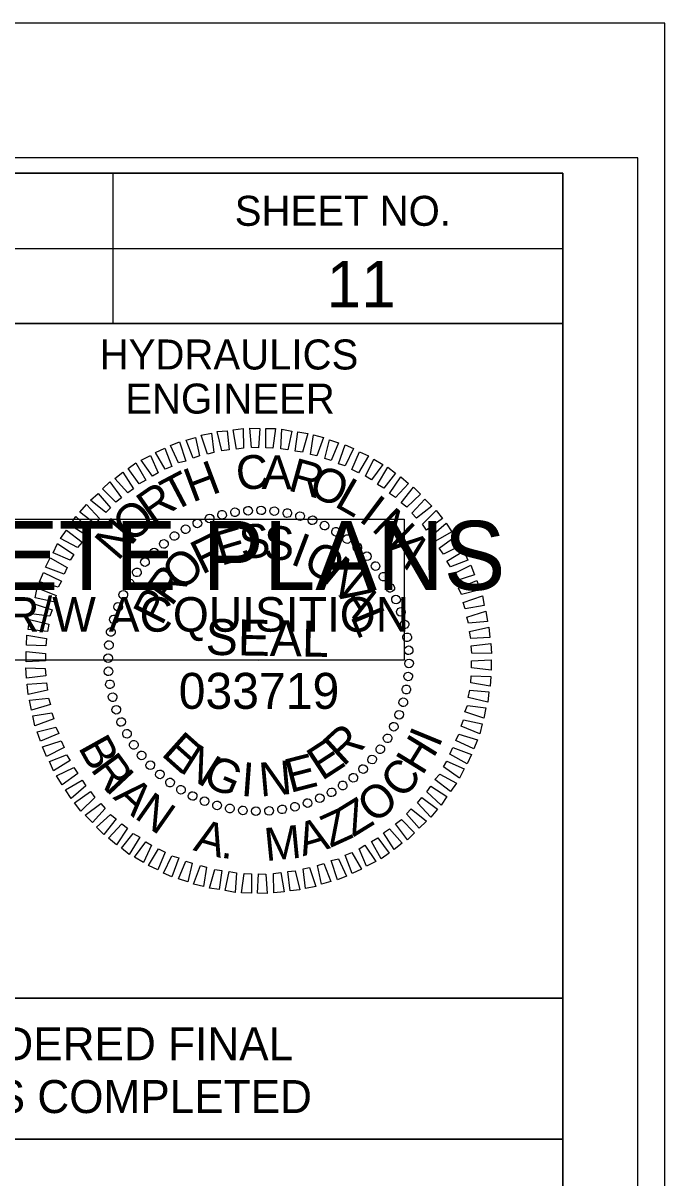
# Model space of a CAD drawing. Extents: x 1779926 to 1781610, y 620464 to 621564.
# Drawn here: x 1781503 to 1781610, y 621371.7 to 621564.2 of the extents above; entities that cross this region are included whole.
import ezdxf

# ---------------------------------------------------------------- set-up
doc = ezdxf.new("R2010")
doc.units = 0
for name, color, linetype in [('Old_Level_58', 7, 'Continuous'), ('Sheet Cutting Line CELL', 7, 'Continuous'), ('Sheet Data Field CELL', 7, 'Continuous'), ('Sheet Plot Border Inside CELL', 7, 'Continuous'), ('Sheet Plot Border Outside CELL', 7, 'Continuous'), ('Sheet Professional Seal CELL', 7, 'Continuous'), ('Sheet Profile CELL', 7, 'Continuous'), ('Sheet Profile Grid Major CELL', 7, 'Continuous'), ('Sheet Profile Grid Minor CELL', 7, 'Continuous'), ('Sheet Sticker Exception Certification CELL', 7, 'Continuous'), ('Sheet Sticker Incomplete CELL', 7, 'Continuous')]:
    doc.layers.add(name, color=color, linetype=linetype)

msp = doc.modelspace()

# ---------------------------------------------------------------- linework, layer by layer
at = {"layer": 'Old_Level_58'}
msp.add_lwpolyline([(1781392.96, 621378.13), (1781592.95, 621378.13), (1781592.95, 621314.19), (1781392.96, 621314.19)], close=True, dxfattribs=at)
at = {"layer": 'Sheet Cutting Line CELL'}
msp.add_line((1781609.96, 621564.19), (1779925.96, 621564.19), dxfattribs=at)
at = {"layer": 'Sheet Plot Border Inside CELL'}
msp.add_lwpolyline([(1779938.96, 620486.64), (1781605.46, 620486.64), (1781605.46, 621541.74), (1779938.96, 621541.74)], close=True, dxfattribs=at)
at = {"layer": 'Sheet Plot Border Outside CELL'}
msp.add_lwpolyline([(1779925.96, 620464.19), (1781609.96, 620464.19), (1781609.96, 621564.19), (1779925.96, 621564.19)], close=True, dxfattribs=at)
at = {"layer": 'Sheet Professional Seal CELL'}
for p, q in [((1781538.34, 621482.64), (1781538.34, 621482.64)), ((1781540.49, 621482.94), (1781540.49, 621482.94)), ((1781542.69, 621482.99), (1781542.69, 621482.99)), ((1781544.89, 621482.84), (1781544.89, 621482.84)), ((1781547.04, 621482.49), (1781547.04, 621482.49)), ((1781532.04, 621480.84), (1781532.04, 621480.84)), ((1781534.04, 621481.64), (1781534.04, 621481.64)), ((1781536.14, 621482.24), (1781536.14, 621482.24)), ((1781549.14, 621482.04), (1781549.14, 621482.04)), ((1781551.24, 621481.34), (1781551.24, 621481.34)), ((1781528.19, 621478.69), (1781528.19, 621478.69)), ((1781530.09, 621479.84), (1781530.09, 621479.84)), ((1781553.24, 621480.44), (1781553.24, 621480.44)), ((1781555.19, 621479.44), (1781555.19, 621479.44)), ((1781526.44, 621477.44), (1781526.44, 621477.44)), ((1781556.99, 621478.19), (1781556.99, 621478.19)), ((1781558.74, 621476.84), (1781558.74, 621476.84)), ((1781524.79, 621475.94), (1781524.79, 621475.94)), ((1781560.29, 621475.34), (1781560.29, 621475.34)), ((1781523.29, 621474.39), (1781523.29, 621474.39)), ((1781561.79, 621473.69), (1781561.79, 621473.69)), ((1781521.94, 621472.64), (1781521.94, 621472.64)), ((1781563.04, 621471.94), (1781563.04, 621471.94)), ((1781520.69, 621470.84), (1781520.69, 621470.84)), ((1781564.19, 621470.04), (1781564.19, 621470.04)), ((1781519.69, 621468.89), (1781519.69, 621468.89)), ((1781565.19, 621468.09), (1781565.19, 621468.09)), ((1781518.79, 621466.89), (1781518.79, 621466.89)), ((1781565.99, 621466.09), (1781565.99, 621466.09)), ((1781518.09, 621464.79), (1781518.09, 621464.79)), ((1781566.59, 621463.99), (1781566.59, 621463.99)), ((1781517.64, 621462.69), (1781517.64, 621462.69)), ((1781566.99, 621461.79), (1781566.99, 621461.79)), ((1781517.29, 621460.54), (1781517.29, 621460.54)), ((1781567.29, 621459.64), (1781567.29, 621459.64)), ((1781517.14, 621458.34), (1781517.14, 621458.34)), ((1781542.24, 621457.89), (1781542.24, 621457.89)), ((1781567.34, 621457.44), (1781567.34, 621457.44)), ((1781517.19, 621456.14), (1781517.19, 621456.14)), ((1781517.49, 621453.99), (1781517.49, 621453.99)), ((1781567.19, 621455.24), (1781567.19, 621455.24)), ((1781517.89, 621451.79), (1781517.89, 621451.79)), ((1781566.84, 621453.09), (1781566.84, 621453.09)), ((1781518.49, 621449.69), (1781518.49, 621449.69)), ((1781566.39, 621450.99), (1781566.39, 621450.99)), ((1781565.69, 621448.89), (1781565.69, 621448.89)), ((1781519.29, 621447.69), (1781519.29, 621447.69)), ((1781564.79, 621446.89), (1781564.79, 621446.89)), ((1781520.29, 621445.74), (1781520.29, 621445.74)), ((1781563.79, 621444.94), (1781563.79, 621444.94)), ((1781521.44, 621443.84), (1781521.44, 621443.84)), ((1781522.69, 621442.09), (1781522.69, 621442.09)), ((1781562.54, 621443.14), (1781562.54, 621443.14)), ((1781524.19, 621440.44), (1781524.19, 621440.44)), ((1781561.19, 621441.39), (1781561.19, 621441.39)), ((1781525.74, 621438.94), (1781525.74, 621438.94)), ((1781558.04, 621438.34), (1781558.04, 621438.34)), ((1781559.69, 621439.84), (1781559.69, 621439.84)), ((1781527.49, 621437.59), (1781527.49, 621437.59)), ((1781529.29, 621436.34), (1781529.29, 621436.34)), ((1781556.29, 621437.09), (1781556.29, 621437.09)), ((1781531.24, 621435.34), (1781531.24, 621435.34)), ((1781533.24, 621434.44), (1781533.24, 621434.44)), ((1781552.44, 621434.94), (1781552.44, 621434.94)), ((1781554.39, 621435.94), (1781554.39, 621435.94)), ((1781535.34, 621433.74), (1781535.34, 621433.74)), ((1781537.44, 621433.29), (1781537.44, 621433.29)), ((1781539.59, 621432.94), (1781539.59, 621432.94)), ((1781541.79, 621432.79), (1781541.79, 621432.79)), ((1781543.99, 621432.84), (1781543.99, 621432.84)), ((1781546.14, 621433.14), (1781546.14, 621433.14)), ((1781548.34, 621433.54), (1781548.34, 621433.54)), ((1781550.44, 621434.14), (1781550.44, 621434.14))]:
    msp.add_line(p, q, dxfattribs=at)
for points in [[(1781536.14, 621492.89), (1781535.34, 621496.09), (1781536.99, 621496.24), (1781537.34, 621493.04)], [(1781538.54, 621493.19), (1781537.99, 621496.39), (1781539.69, 621496.59), (1781539.74, 621493.34)], [(1781541.04, 621493.44), (1781540.79, 621496.69), (1781542.44, 621496.64), (1781542.24, 621493.39)], [(1781543.44, 621493.39), (1781543.44, 621496.64), (1781545.09, 621496.59), (1781544.64, 621493.34)], [(1781545.94, 621493.24), (1781546.14, 621496.49), (1781547.79, 621496.19), (1781547.14, 621493.04)], [(1781548.34, 621492.84), (1781548.79, 621496.04), (1781550.44, 621495.79), (1781549.54, 621492.69)], [(1781528.89, 621490.89), (1781527.59, 621493.79), (1781529.09, 621494.39), (1781530.14, 621491.19)], [(1781531.34, 621491.69), (1781530.19, 621494.69), (1781531.74, 621495.14), (1781532.39, 621492.04)], [(1781533.74, 621492.34), (1781532.69, 621495.49), (1781534.39, 621495.84), (1781534.79, 621492.59)], [(1781550.89, 621492.29), (1781551.39, 621495.54), (1781553.09, 621495.14), (1781551.94, 621492.04)], [(1781553.29, 621491.64), (1781554.04, 621494.74), (1781555.59, 621494.24), (1781554.34, 621491.29)], [(1781524.54, 621488.64), (1781522.69, 621491.34), (1781524.24, 621492.14), (1781525.49, 621489.24)], [(1781526.69, 621489.84), (1781525.09, 621492.64), (1781526.64, 621493.34), (1781527.79, 621490.29)], [(1781555.54, 621490.74), (1781556.69, 621493.89), (1781558.09, 621493.29), (1781556.69, 621490.39)], [(1781557.79, 621489.79), (1781559.04, 621492.74), (1781560.59, 621492.04), (1781558.89, 621489.24)], [(1781522.34, 621487.39), (1781520.49, 621489.94), (1781521.79, 621490.89), (1781523.44, 621487.99)], [(1781560.09, 621488.64), (1781561.44, 621491.49), (1781562.94, 621490.64), (1781561.04, 621488.04)], [(1781562.04, 621487.29), (1781563.79, 621490.19), (1781565.09, 621489.14), (1781563.14, 621486.69)], [(1781520.44, 621485.89), (1781518.29, 621488.29), (1781519.64, 621489.34), (1781521.39, 621486.54)], [(1781564.09, 621485.79), (1781565.94, 621488.54), (1781567.24, 621487.44), (1781565.04, 621485.09)], [(1781518.44, 621484.34), (1781516.24, 621486.54), (1781517.44, 621487.74), (1781519.39, 621485.04)], [(1781565.99, 621484.24), (1781568.04, 621486.84), (1781569.24, 621485.64), (1781566.94, 621483.49)], [(1781516.79, 621482.59), (1781514.24, 621484.64), (1781515.49, 621485.79), (1781517.59, 621483.39)], [(1781567.79, 621482.49), (1781569.94, 621484.84), (1781571.14, 621483.64), (1781568.54, 621481.69)], [(1781515.04, 621480.69), (1781512.44, 621482.64), (1781513.54, 621483.94), (1781515.74, 621481.59)], [(1781569.54, 621480.69), (1781571.84, 621482.94), (1781572.89, 621481.59), (1781570.24, 621479.69)], [(1781513.54, 621478.79), (1781510.84, 621480.49), (1781511.79, 621481.94), (1781514.19, 621479.74)], [(1781571.04, 621478.74), (1781573.49, 621480.84), (1781574.44, 621479.39), (1781571.64, 621477.79)], [(1781512.04, 621476.79), (1781509.24, 621478.29), (1781510.24, 621479.69), (1781512.84, 621477.69)], [(1781572.34, 621476.69), (1781574.99, 621478.59), (1781575.94, 621477.09), (1781573.04, 621475.69)], [(1781510.84, 621474.64), (1781507.99, 621475.89), (1781508.74, 621477.44), (1781511.44, 621475.59)], [(1781509.84, 621472.34), (1781506.74, 621473.49), (1781507.49, 621475.04), (1781510.34, 621473.44)], [(1781573.64, 621474.49), (1781576.44, 621476.24), (1781577.09, 621474.69), (1781574.24, 621473.54)], [(1781574.64, 621472.34), (1781577.59, 621473.84), (1781578.24, 621472.24), (1781575.14, 621471.24)], [(1781508.84, 621470.14), (1781505.74, 621471.04), (1781506.39, 621472.59), (1781509.39, 621471.19)], [(1781575.54, 621469.99), (1781578.59, 621471.29), (1781579.14, 621469.74), (1781576.04, 621468.94)], [(1781508.09, 621467.74), (1781504.99, 621468.39), (1781505.34, 621470.04), (1781508.49, 621468.79)], [(1781507.44, 621465.34), (1781504.34, 621465.74), (1781504.69, 621467.44), (1781507.84, 621466.39)], [(1781576.34, 621467.59), (1781579.54, 621468.74), (1781579.84, 621467.09), (1781576.69, 621466.54)], [(1781576.94, 621465.19), (1781580.09, 621466.14), (1781580.39, 621464.44), (1781577.24, 621464.14)], [(1781507.04, 621462.79), (1781503.84, 621463.09), (1781504.04, 621464.79), (1781507.29, 621463.99)], [(1781577.39, 621462.79), (1781580.64, 621463.49), (1781580.79, 621461.79), (1781577.59, 621461.59)], [(1781506.79, 621460.39), (1781503.54, 621460.49), (1781503.64, 621462.14), (1781506.89, 621461.59)], [(1781506.74, 621457.89), (1781503.49, 621457.74), (1781503.49, 621459.44), (1781506.74, 621459.09)], [(1781577.69, 621460.39), (1781580.94, 621460.79), (1781581.04, 621459.09), (1781577.79, 621459.19)], [(1781577.74, 621457.89), (1781580.99, 621458.04), (1781580.99, 621456.34), (1781577.74, 621456.69)], [(1781506.79, 621455.39), (1781503.54, 621454.99), (1781503.44, 621456.69), (1781506.69, 621456.59)], [(1781507.09, 621452.99), (1781503.84, 621452.29), (1781503.69, 621453.99), (1781506.89, 621454.19)], [(1781577.69, 621455.39), (1781580.94, 621455.29), (1781580.84, 621453.64), (1781577.59, 621454.19)], [(1781507.54, 621450.59), (1781504.39, 621449.64), (1781504.09, 621451.34), (1781507.24, 621451.64)], [(1781577.44, 621452.99), (1781580.64, 621452.69), (1781580.44, 621450.99), (1781577.19, 621451.79)], [(1781577.04, 621450.44), (1781580.14, 621450.04), (1781579.79, 621448.34), (1781576.64, 621449.39)], [(1781508.14, 621448.19), (1781504.94, 621447.04), (1781504.64, 621448.69), (1781507.79, 621449.24)], [(1781576.39, 621448.04), (1781579.49, 621447.39), (1781579.14, 621445.74), (1781575.99, 621446.99)], [(1781508.94, 621445.79), (1781505.89, 621444.49), (1781505.34, 621446.04), (1781508.44, 621446.84)], [(1781509.84, 621443.44), (1781506.89, 621441.94), (1781506.24, 621443.54), (1781509.34, 621444.54)], [(1781575.64, 621445.64), (1781578.74, 621444.74), (1781578.09, 621443.19), (1781575.09, 621444.59)], [(1781510.84, 621441.29), (1781508.04, 621439.54), (1781507.39, 621441.09), (1781510.24, 621442.24)], [(1781574.64, 621443.44), (1781577.74, 621442.29), (1781576.99, 621440.74), (1781574.14, 621442.34)], [(1781512.14, 621439.09), (1781509.49, 621437.19), (1781508.54, 621438.69), (1781511.44, 621440.09)], [(1781573.64, 621441.14), (1781576.49, 621439.89), (1781575.74, 621438.34), (1781573.04, 621440.19)], [(1781572.44, 621438.99), (1781575.24, 621437.49), (1781574.24, 621436.09), (1781571.64, 621438.09)], [(1781513.44, 621437.04), (1781510.99, 621434.94), (1781510.04, 621436.39), (1781512.84, 621437.99)], [(1781570.94, 621436.99), (1781573.64, 621435.29), (1781572.69, 621433.84), (1781570.29, 621436.04)], [(1781514.94, 621435.09), (1781512.64, 621432.84), (1781511.59, 621434.19), (1781514.24, 621436.09)], [(1781569.44, 621435.09), (1781572.04, 621433.14), (1781570.94, 621431.84), (1781568.74, 621434.19)], [(1781516.69, 621433.29), (1781514.54, 621430.94), (1781513.34, 621432.14), (1781515.94, 621434.09)], [(1781567.69, 621433.19), (1781570.24, 621431.14), (1781568.99, 621429.99), (1781566.89, 621432.39)], [(1781518.49, 621431.54), (1781516.44, 621428.94), (1781515.24, 621430.14), (1781517.54, 621432.29)], [(1781520.39, 621429.99), (1781518.54, 621427.24), (1781517.24, 621428.34), (1781519.44, 621430.69)], [(1781566.04, 621431.44), (1781568.24, 621429.24), (1781567.04, 621428.04), (1781565.09, 621430.74)], [(1781522.44, 621428.49), (1781520.69, 621425.59), (1781519.39, 621426.64), (1781521.34, 621429.09)], [(1781564.04, 621429.89), (1781566.19, 621427.49), (1781564.84, 621426.44), (1781563.09, 621429.24)], [(1781524.39, 621427.14), (1781523.04, 621424.29), (1781521.54, 621425.14), (1781523.44, 621427.74)], [(1781559.94, 621427.14), (1781561.79, 621424.44), (1781560.24, 621423.64), (1781558.99, 621426.54)], [(1781562.14, 621428.39), (1781563.99, 621425.84), (1781562.69, 621424.89), (1781561.04, 621427.79)], [(1781526.69, 621425.99), (1781525.44, 621423.04), (1781523.89, 621423.74), (1781525.59, 621426.54)], [(1781528.94, 621425.04), (1781527.79, 621421.89), (1781526.39, 621422.49), (1781527.79, 621425.39)], [(1781555.59, 621424.89), (1781556.89, 621421.99), (1781555.39, 621421.39), (1781554.34, 621424.59)], [(1781557.79, 621425.94), (1781559.39, 621423.14), (1781557.84, 621422.44), (1781556.69, 621425.49)], [(1781531.19, 621424.14), (1781530.44, 621421.04), (1781528.89, 621421.54), (1781530.14, 621424.49)], [(1781533.59, 621423.49), (1781533.09, 621420.24), (1781531.39, 621420.64), (1781532.54, 621423.74)], [(1781536.14, 621422.94), (1781535.69, 621419.74), (1781534.04, 621419.99), (1781534.94, 621423.09)], [(1781538.54, 621422.54), (1781538.34, 621419.29), (1781536.69, 621419.59), (1781537.34, 621422.74)], [(1781548.34, 621422.89), (1781549.14, 621419.69), (1781547.49, 621419.54), (1781547.14, 621422.74)], [(1781550.74, 621423.44), (1781551.79, 621420.29), (1781550.09, 621419.94), (1781549.69, 621423.19)], [(1781553.14, 621424.09), (1781554.29, 621421.09), (1781552.74, 621420.64), (1781552.09, 621423.74)], [(1781541.04, 621422.39), (1781541.04, 621419.14), (1781539.39, 621419.19), (1781539.84, 621422.44)], [(1781543.44, 621422.34), (1781543.69, 621419.09), (1781542.04, 621419.14), (1781542.24, 621422.39)], [(1781545.94, 621422.59), (1781546.49, 621419.39), (1781544.79, 621419.19), (1781544.74, 621422.44)]]:
    msp.add_lwpolyline(points, close=True, dxfattribs=at)
for centre, major_axis in [((1781534.08, 621481.61), (-0.234, 0.681)), ((1781536.17, 621482.23), (-0.174, 0.699)), ((1781538.32, 621482.66), (-0.113, 0.711)), ((1781540.49, 621482.91), (-0.05, 0.718)), ((1781542.68, 621482.97), (0.013, 0.72)), ((1781544.86, 621482.83), (0.075, 0.716)), ((1781547.03, 621482.51), (0.137, 0.707)), ((1781549.16, 621482), (0.198, 0.692)), ((1781530.08, 621479.83), (-0.349, 0.63)), ((1781532.04, 621480.8), (-0.293, 0.658)), ((1781551.23, 621481.31), (0.258, 0.672)), ((1781553.24, 621480.43), (0.316, 0.647)), ((1781528.22, 621478.68), (-0.403, 0.597)), ((1781555.16, 621479.39), (0.371, 0.617)), ((1781556.98, 621478.18), (0.423, 0.582)), ((1781524.82, 621475.93), (-0.5, 0.518)), ((1781526.46, 621477.38), (-0.453, 0.56)), ((1781558.7, 621476.82), (0.472, 0.543)), ((1781523.31, 621474.35), (-0.543, 0.472)), ((1781560.28, 621475.31), (0.518, 0.5)), ((1781521.95, 621472.63), (-0.582, 0.423)), ((1781561.73, 621473.67), (0.56, 0.453)), ((1781520.74, 621470.81), (-0.617, 0.371)), ((1781563.03, 621471.92), (0.597, 0.403)), ((1781564.18, 621470.05), (0.63, 0.349)), ((1781519.7, 621468.89), (-0.647, 0.316)), ((1781518.83, 621466.88), (-0.672, 0.258)), ((1781565.15, 621468.09), (0.658, 0.293)), ((1781518.13, 621464.8), (-0.692, 0.198)), ((1781565.96, 621466.06), (0.681, 0.234)), ((1781517.62, 621462.68), (-0.707, 0.137)), ((1781566.58, 621463.96), (0.699, 0.174)), ((1781517.3, 621460.51), (-0.716, 0.075)), ((1781567.01, 621461.81), (0.711, 0.113)), ((1781567.26, 621459.64), (0.718, 0.05)), ((1781517.17, 621458.33), (-0.72, 0.013)), ((1781567.32, 621457.45), (0.72, -0.013)), ((1781517.22, 621456.14), (-0.718, -0.05)), ((1781567.18, 621455.27), (0.716, -0.075)), ((1781517.47, 621453.97), (-0.711, -0.113)), ((1781566.86, 621453.11), (0.707, -0.137)), ((1781517.91, 621451.82), (-0.699, -0.174)), ((1781566.35, 621450.98), (0.692, -0.198)), ((1781518.53, 621449.73), (-0.681, -0.234)), ((1781565.66, 621448.9), (0.672, -0.258)), ((1781519.33, 621447.69), (-0.658, -0.293)), ((1781520.31, 621445.73), (-0.63, -0.349)), ((1781564.78, 621446.9), (0.647, -0.316)), ((1781521.45, 621443.87), (-0.597, -0.403)), ((1781562.53, 621443.15), (0.582, -0.423)), ((1781563.74, 621444.97), (0.617, -0.371)), ((1781522.75, 621442.11), (-0.56, -0.453)), ((1781561.17, 621441.44), (0.543, -0.472)), ((1781524.2, 621440.47), (-0.518, -0.5)), ((1781559.66, 621439.85), (0.5, -0.518)), ((1781525.79, 621438.96), (-0.472, -0.543)), ((1781527.5, 621437.6), (-0.423, -0.582)), ((1781558.03, 621438.4), (0.453, -0.56)), ((1781529.32, 621436.39), (-0.371, -0.617)), ((1781554.4, 621435.96), (0.349, -0.63)), ((1781556.27, 621437.1), (0.403, -0.597)), ((1781531.25, 621435.35), (-0.316, -0.647)), ((1781533.25, 621434.48), (-0.258, -0.672)), ((1781535.33, 621433.78), (-0.198, -0.692)), ((1781548.31, 621433.56), (0.174, -0.699)), ((1781550.41, 621434.18), (0.234, -0.681)), ((1781552.44, 621434.98), (0.293, -0.658)), ((1781537.46, 621433.27), (-0.137, -0.707)), ((1781539.62, 621432.95), (-0.075, -0.716)), ((1781541.8, 621432.82), (-0.013, -0.72)), ((1781543.99, 621432.87), (0.05, -0.718)), ((1781546.17, 621433.12), (0.113, -0.711))]:
    msp.add_ellipse(centre, major_axis=major_axis, ratio=0.999708, dxfattribs=at)
at = {"layer": 'Sheet Profile CELL'}
for p, q in [((1781517.96, 621539.14), (1781517.96, 621514.14)), ((1781392.91, 621526.64), (1781592.96, 621526.64))]:
    msp.add_line(p, q, dxfattribs=at)
for points in [[(1781592.96, 621539.19), (1780092.96, 621539.19), (1780092.96, 620489.19), (1781592.96, 620489.19)], [(1781392.91, 621539.19), (1781592.96, 621539.19), (1781592.96, 621514.14), (1781392.91, 621514.14)], [(1781492.96, 621514.14), (1781592.96, 621514.14), (1781592.96, 621401.64), (1781492.96, 621401.64)]]:
    msp.add_lwpolyline(points, close=True, dxfattribs=at)
at = {"layer": 'Sheet Profile Grid Major CELL'}
msp.add_lwpolyline([(1781542.96, 621314.19), (1781542.96, 621039.19), (1781592.96, 621039.19), (1781592.96, 621389.19)], dxfattribs=at)
at = {"layer": 'Sheet Sticker Exception Certification CELL'}
for p, q in [((1781392.91, 621401.64), (1781592.95, 621401.64)), ((1781392.91, 621401.64), (1781592.95, 621401.64)), ((1781592.95, 621401.63), (1781592.95, 621378.13)), ((1781592.95, 621401.63), (1781592.95, 621378.13)), ((1781592.95, 621378.14), (1781392.91, 621378.14)), ((1781592.95, 621378.14), (1781392.91, 621378.14))]:
    msp.add_line(p, q, dxfattribs=at)
at = {"layer": 'Sheet Sticker Incomplete CELL'}
msp.add_lwpolyline([(1781419.48, 621457.99), (1781419.48, 621481.49), (1781566.48, 621481.49), (1781566.48, 621457.99)], close=True, dxfattribs=at)

# ---------------------------------------------------------------- texts
at = {"layer": 'Sheet Data Field CELL'}
msp.add_text('11', height=7.75, dxfattribs=at).set_placement((1781553.58, 621516.8))
at = {"layer": 'Sheet Professional Seal CELL'}
for s, height, rotation, p in [('C', 5.64, 6.2199, (1781538.79, 621486.24)), ('A', 5.64, 359.0203, (1781542.74, 621486.54)), ('H', 5.64, 20.6195, (1781531.19, 621484.24)), ('R', 5.64, 344.6211, (1781546.94, 621486.34)), ('O', 5.64, 337.4212, (1781550.29, 621485.59)), ('T', 5.64, 27.8198, (1781527.94, 621482.59)), ('L', 5.64, 330.2209, (1781554.69, 621483.74)), ('R', 5.64, 35.0205, (1781524.54, 621480.39)), ('I', 5.64, 323.0201, (1781558.74, 621481.34)), ('O', 5.64, 42.2217, (1781521.09, 621477.29)), ('N', 5.64, 315.8189, (1781560.89, 621479.79)), ('N', 5.64, 49.4235, (1781518.79, 621474.39)), ('S', 5.64, 7.2556, (1781539.44, 621474.74)), ('F', 5.64, 25.967, (1781532.79, 621472.19)), ('E', 5.64, 16.6111, (1781535.99, 621473.69)), ('S', 5.64, 357.9004, (1781543.04, 621474.79)), ('I', 5.64, 339.1896, (1781547.34, 621474.09)), ('A', 5.64, 308.6172, (1781563.84, 621476.84)), ('O', 5.64, 329.8335, (1781549.34, 621473.39)), ('O', 5.64, 44.6812, (1781529.49, 621469.24)), ('N', 5.64, 320.4766, (1781552.69, 621471.39)), ('R', 5.64, 54.0397, (1781527.74, 621466.79)), ('P', 5.64, 63.3989, (1781526.14, 621463.59)), ('A', 5.64, 301.7603, (1781555.54, 621468.79)), ('L', 5.64, 292.4008, (1781557.49, 621465.34)), ('SEAL', 5.998, 359, (1781533.39, 621458.89)), ('E', 5.64, 318.2769, (1781525.84, 621442.24)), ('R', 5.64, 42.4814, (1781556.34, 621440.14)), ('N', 5.64, 327.634, (1781528.84, 621439.54)), ('E', 5.64, 33.1241, (1781552.79, 621437.79)), ('E', 5.64, 14.4118, (1781547.49, 621435.84)), ('G', 5.64, 336.9902, (1781532.64, 621437.29)), ('I', 5.64, 355.7012, (1781539.19, 621435.39)), ('N', 5.64, 5.0564, (1781542.54, 621435.24))]:
    msp.add_text(s, height=height, rotation=rotation, dxfattribs=at).set_placement(p)
at = {"layer": 'Sheet Profile CELL'}
for s, p in [('SHEET NO.', (1781538.27, 621530.4)), ('HYDRAULICS', (1781515.77, 621506.45)), ('ENGINEER', (1781520.02, 621499.1))]:
    msp.add_text(s, height=5, dxfattribs=at).set_placement(p)
at = {"layer": 'Sheet Profile Grid Minor CELL'}
msp.add_text('033719', height=5.998, dxfattribs=at).set_placement((1781528.93, 621449.88))
for s, rotation, p in [('I', 67.5926, (1781572.3, 621443.26)), ('B', 299.1529, (1781512.09, 621443.45)), ('H', 58.3478, (1781569.55, 621438.62)), ('R', 306.2797, (1781514.12, 621439.82)), ('C', 49.4751, (1781566.25, 621434.64)), ('I', 313.2061, (1781516.5, 621436.56)), ('A', 316.7266, (1781517.86, 621435.02)), ('O', 38.7706, (1781561.52, 621430.58)), ('N', 324.9124, (1781521.37, 621431.78)), ('Z', 31.6438, (1781557.98, 621428.4)), ('Z', 24.517, (1781554.2, 621426.67)), ('A', 344.2893, (1781531.21, 621426.34)), ('M', 5.6554, (1781543.46, 621424.49)), ('A', 16.3312, (1781549.63, 621425.29)), ('.', 352.4751, (1781535.82, 621425.09))]:
    msp.add_text(s, height=5.5, rotation=rotation, dxfattribs=at).set_placement(p)
at = {"layer": 'Sheet Sticker Exception Certification CELL'}
for s, p in [('DOCUMENT NOT CONSIDERED FINAL', (1781413.98, 621391.3)), ('DOCUMENT NOT CONSIDERED FINAL', (1781413.98, 621391.3)), ('UNLESS ALL SIGNATURES COMPLETED', (1781408.91, 621382.5)), ('UNLESS ALL SIGNATURES COMPLETED', (1781408.91, 621382.5))]:
    msp.add_text(s, height=5.5, dxfattribs=at).set_placement(p)
at = {"layer": 'Sheet Sticker Incomplete CELL'}
for s, height, p in [('INCOMPLETE PLANS', 11.52, (1781428.43, 621469.69)), ('DO NOT USE FOR R/W ACQUISITION', 5.76, (1781431.68, 621462.74))]:
    msp.add_text(s, height=height, dxfattribs=at).set_placement(p)

doc.saveas('drawing.dxf')
